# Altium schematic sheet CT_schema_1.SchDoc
size 402 x 258 mm
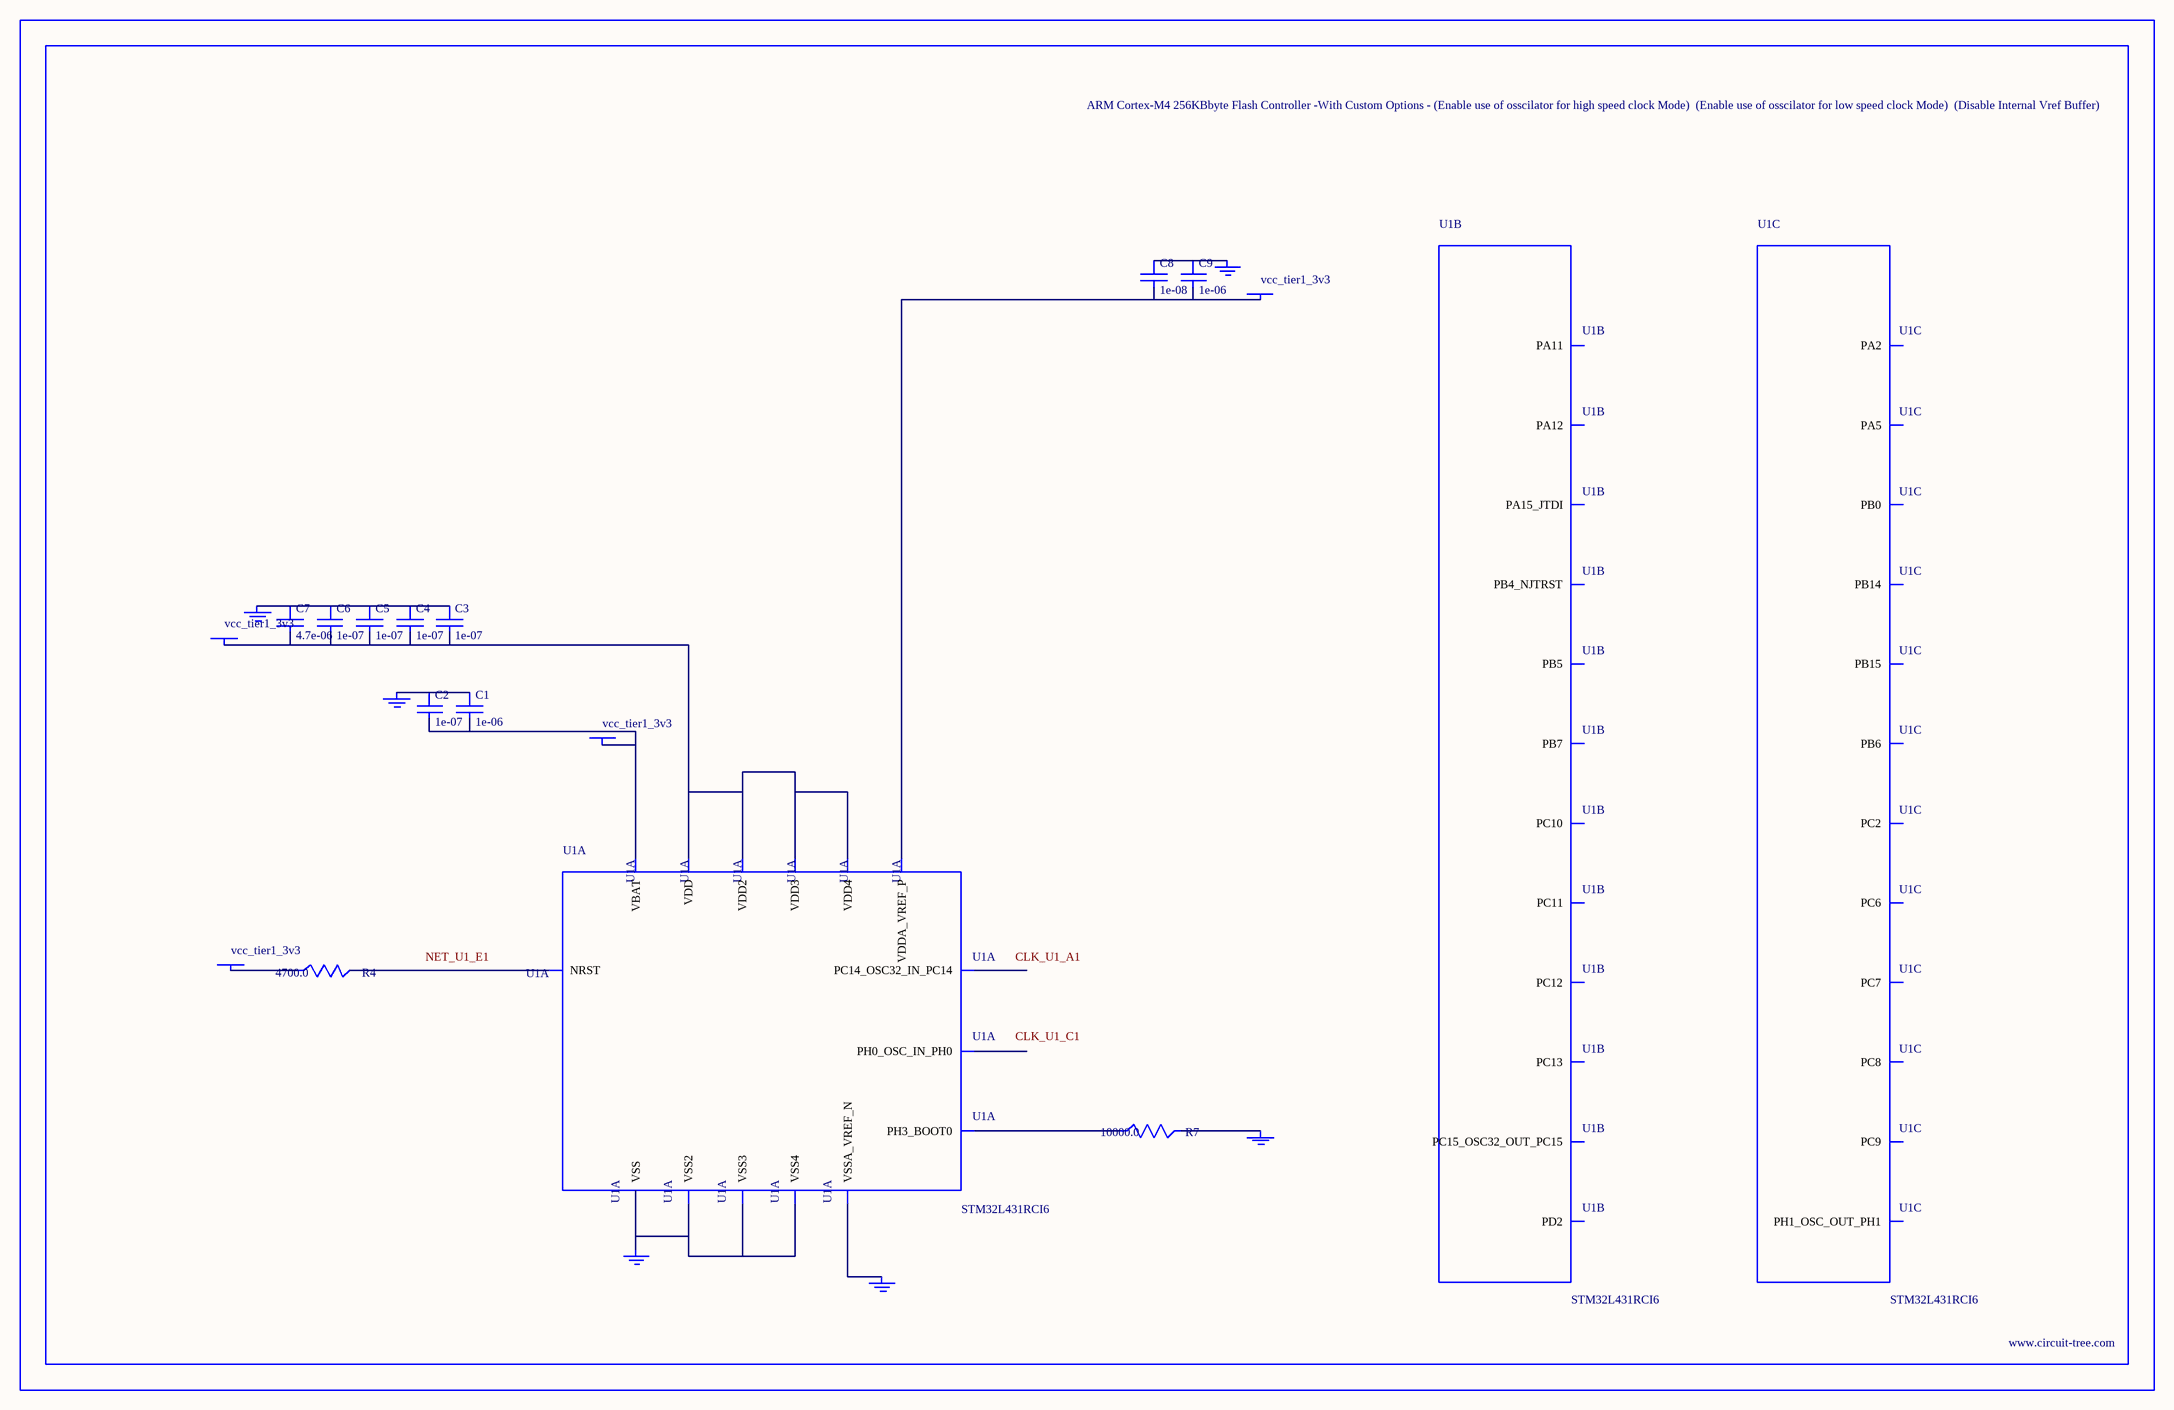
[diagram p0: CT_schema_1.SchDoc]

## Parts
BORDER0  (no value)
C1  1e-06  [C0603]
C2  1e-07  [C0603]
C3  1e-07  [C0603]
C4  1e-07  [C0603]
C5  1e-07  [C0603]
C6  1e-07  [C0603]
C7  4.7e-06  [C0603]
C8  1e-08  [C0603]
C9  1e-06  [C0603]
GND_INSTANCE_0_0  (no value)
GND_INSTANCE_0_1  (no value)
GND_INSTANCE_0_2  (no value)
GND_INSTANCE_0_3  (no value)
GND_INSTANCE_0_4  (no value)
GND_INSTANCE_0_5  (no value)
POWER_INSTANCE_0_0  vcc_tier1_3v3
POWER_INSTANCE_0_1  vcc_tier1_3v3
POWER_INSTANCE_0_2  vcc_tier1_3v3
POWER_INSTANCE_0_3  vcc_tier1_3v3
R4  4700.0  [R0603]
R7  10000.0  [R0603]
U1  STM32L431RCI6  [UFBGA64]  (parts A,B,C of 6)

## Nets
NetC1_1: C1.1 C2.1 GND_INSTANCE_0_0.0(GND)
NetC1_2: C1.2 C2.2 POWER_INSTANCE_0_0.0(PWR) U1.B2(VBAT)
NetC3_1: C3.1 C4.1 C5.1 C6.1 C7.1 GND_INSTANCE_0_1.0(GND)
NetC3_2: C3.2 C4.2 C5.2 C6.2 C7.2 POWER_INSTANCE_0_1.0(PWR) U1.D2(VDD) U1.E4(VDD2) U1.E5(VDD3) U1.E6(VDD4)
NetC8_1: C8.1 C9.1 GND_INSTANCE_0_3.0(GND)
NetC8_2: C8.2 C9.2 POWER_INSTANCE_0_2.0(PWR) U1.H1(VDDA_VREF_P)
NetGND_INSTANCE_0_2_0: GND_INSTANCE_0_2.0(GND) R7.2
NetGND_INSTANCE_0_4_0: GND_INSTANCE_0_4.0(GND) U1.F1(VSSA_VREF_N)
NetGND_INSTANCE_0_5_0: GND_INSTANCE_0_5.0(GND) U1.C2(VSS) U1.D4(VSS2) U1.D5(VSS3) U1.D6(VSS4)
NetPOWER_INSTANCE_0_3_0: POWER_INSTANCE_0_3.0(PWR) R4.1
NetR4_2: R4.2 U1.E1(NRST)
NetR7_1: R7.1 U1.B4(PH3_BOOT0)

Not connected (* = marked no-connect by the designer): U1 A1(PC14_OSC32_IN_PC14) A2(PC13) A4(PB4_NJTRST) A6(PA15_JTDI) B1(PC15_OSC32_OUT_PC15) B5(PD2) B6(PC11) B7(PC10) B8(PA12) C1(PH0_OSC_IN_PH0) C3(PB7) C4(PB5) C5(PC12) C8(PA11) D1(PH1_OSC_OUT_PH1) D3(PB6) D8(PC9) E7(PC7) E8(PC8) F2(PC2) F3(PA2) F4(PA5) F5(PB0) F6(PC6) F7(PB15) F8(PB14)

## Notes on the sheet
- Labels drawn without touching a wire or pin: CLK_U1_A1, CLK_U1_C1, NET_U1_E1

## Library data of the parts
BORDER0 = BORDER_PAGE0
C1 C9 = C0603C105K3RACTU
C2-C6 = 06035C104K4Z2A
C7 = GRM188R6YA475KE15D
C8 = 06035C103K4Z2A
GND_INSTANCE_0_0-GND_INSTANCE_0_5 = GND
POWER_INSTANCE_0_0-POWER_INSTANCE_0_3 = PWR
R4 = RC0603JR-074K7L
R7 = RC0603JR-0710KL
